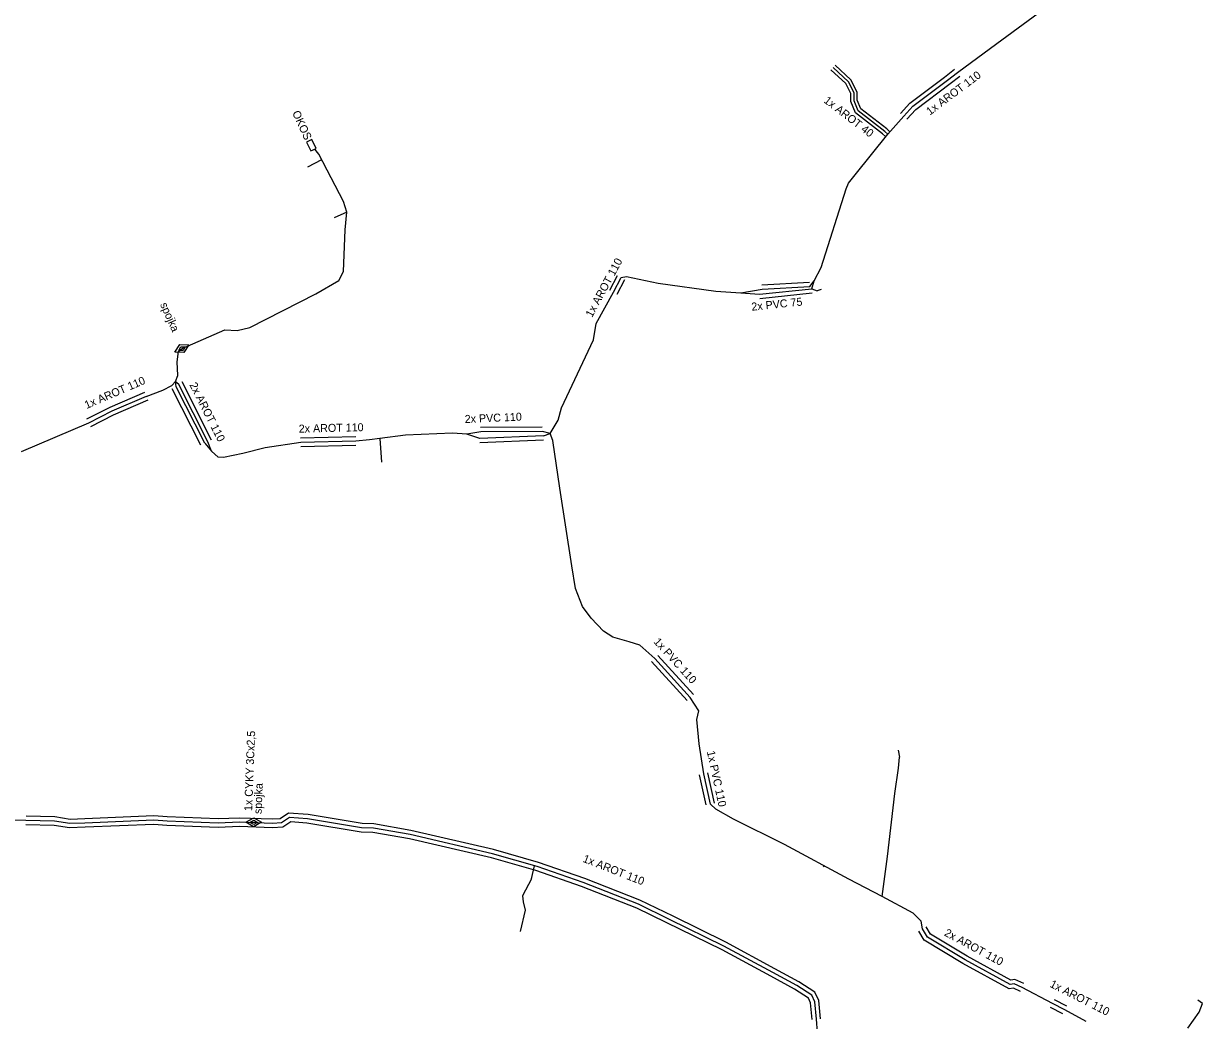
# Model space of a CAD drawing. Extents: x -651943 to -618711, y -1138561 to -1100552.
# Drawn here: x -651118.5 to -651008.1, y -1113424.7 to -1113331.3 of the extents above; entities that cross this region are included whole.
import ezdxf

# ---------------------------------------------------------------- set-up
doc = ezdxf.new("R2010")
doc.units = 0
doc.layers.add('KT trasa', color=7, linetype='Continuous')
doc.layers.add('KT zařízení', color=7, linetype='Continuous')

# ---------------------------------------------------------------- blocks, each defined once
blk = doc.blocks.new('TVSPO_1')
at = {"layer": 'KT zařízení'}
for p, q in [((-0.074, 0.002), (0, 0.044)), ((-0.001, -0.041), (-0.074, 0.002)), ((-0.035, 0), (0, 0.02)), ((0.073, 0.001), (-0.001, -0.041)), ((0, 0.044), (0.073, 0.001)), ((0, 0.02), (0.035, 0)), ((0.035, 0), (0, -0.02)), ((0, -0.02), (-0.035, 0))]:
    blk.add_line(p, q, dxfattribs=at)

msp = doc.modelspace()

# ---------------------------------------------------------------- linework, layer by layer
at = {"layer": 'KT trasa'}
for p, q in [((-651027.31, -1113333.15), (-651020.18, -1113327.9)), ((-651031.02, -1113335.89), (-651027.31, -1113333.15)), ((-651041.22, -1113336.74), (-651042.66, -1113335.41)), ((-651031.94, -1113336.61), (-651031.02, -1113335.89)), ((-651040.69, -1113337.79), (-651041.22, -1113336.74)), ((-651035.18, -1113339.04), (-651031.94, -1113336.61)), ((-651040.7, -1113338.54), (-651040.69, -1113337.79)), ((-651040.3, -1113339.48), (-651040.7, -1113338.54)), ((-651037.82, -1113341.39), (-651040.3, -1113339.48)), ((-651036.03, -1113339.98), (-651035.18, -1113339.04)), ((-651037.54, -1113341.66), (-651036.03, -1113339.98)), ((-651040.6, -1113345.48), (-651037.54, -1113341.66)), ((-651037.54, -1113341.66), (-651037.82, -1113341.39)), ((-651090.85, -1113343.52), (-651091.24, -1113343.05)), ((-651091.89, -1113344.7), (-651090.59, -1113344.03)), ((-651088.54, -1113347.97), (-651090.85, -1113343.52)), ((-651041.45, -1113346.78), (-651041.21, -1113346.25)), ((-651041.21, -1113346.25), (-651040.6, -1113345.48)), ((-651043.77, -1113354.14), (-651041.45, -1113346.78)), ((-651088.24, -1113348.95), (-651088.54, -1113347.97)), ((-651088.24, -1113348.95), (-651089.42, -1113349.48)), ((-651088.39, -1113350.61), (-651088.24, -1113348.95)), ((-651088.54, -1113354.51), (-651088.39, -1113350.61)), ((-651044.45, -1113355.41), (-651043.77, -1113354.14)), ((-651088.97, -1113355.37), (-651088.54, -1113354.51)), ((-651063.24, -1113356.45), (-651062.51, -1113355.09)), ((-651062.51, -1113355.09), (-651062.03, -1113355)), ((-651062.03, -1113355), (-651059.06, -1113355.61)), ((-651091.14, -1113356.6), (-651088.97, -1113355.37)), ((-651059.06, -1113355.61), (-651053.66, -1113356.36)), ((-651053.66, -1113356.36), (-651051.32, -1113356.51)), ((-651051.32, -1113356.51), (-651049.32, -1113356.18)), ((-651049.55, -1113356.64), (-651044.66, -1113356.13)), ((-651049.32, -1113356.18), (-651044.83, -1113355.93)), ((-651044.83, -1113355.93), (-651044.45, -1113355.41)), ((-651044.66, -1113356.13), (-651044.45, -1113355.41)), ((-651044.66, -1113356.13), (-651044.17, -1113356.34)), ((-651043.78, -1113356.22), (-651044.17, -1113356.34)), ((-651097.32, -1113359.78), (-651091.14, -1113356.6)), ((-651064.87, -1113359.39), (-651063.24, -1113356.45)), ((-651051.32, -1113356.51), (-651049.55, -1113356.64)), ((-651065.12, -1113360.91), (-651064.87, -1113359.39)), ((-651103.67, -1113361.74), (-651099.65, -1113360)), ((-651099.65, -1113360), (-651098.51, -1113360.04)), ((-651098.51, -1113360.04), (-651097.32, -1113359.78)), ((-651104.02, -1113362.03), (-651103.67, -1113361.74)), ((-651068.13, -1113367.3), (-651065.12, -1113360.91)), ((-651104.14, -1113362.99), (-651104.02, -1113362.03)), ((-651104.06, -1113364.25), (-651104.14, -1113362.99)), ((-651105.49, -1113365.64), (-651104.62, -1113365.2)), ((-651104.62, -1113365.2), (-651104.28, -1113364.84)), ((-651104.28, -1113364.84), (-651104.06, -1113364.25)), ((-651104.22, -1113365.34), (-651104.28, -1113364.84)), ((-651104.28, -1113364.84), (-651104.01, -1113365.05)), ((-651101.26, -1113370.49), (-651104.01, -1113365.05)), ((-651107.03, -1113366.22), (-651110.27, -1113367.62)), ((-651107.03, -1113366.22), (-651105.49, -1113365.64)), ((-651101.55, -1113370.61), (-651104.22, -1113365.34)), ((-651068.44, -1113368.45), (-651068.13, -1113367.3)), ((-651110.27, -1113367.62), (-651112.43, -1113368.73)), ((-651069.17, -1113369.69), (-651068.44, -1113368.45)), ((-651112.43, -1113368.73), (-651118.74, -1113371.4)), ((-651078.34, -1113369.66), (-651082.74, -1113369.85)), ((-651076.98, -1113369.75), (-651078.34, -1113369.66)), ((-651075.69, -1113369.53), (-651076.98, -1113369.75)), ((-651069.91, -1113369.52), (-651075.69, -1113369.53)), ((-651069.17, -1113369.69), (-651069.91, -1113369.52)), ((-651069.81, -1113369.91), (-651069.17, -1113369.69)), ((-651068.94, -1113370.35), (-651069.17, -1113369.69)), ((-651101.55, -1113370.61), (-651100.92, -1113371.36)), ((-651100.92, -1113371.36), (-651101.26, -1113370.49)), ((-651092.55, -1113370.54), (-651095.89, -1113371.03)), ((-651087.38, -1113370.42), (-651092.55, -1113370.54)), ((-651086.12, -1113370.29), (-651087.38, -1113370.42)), ((-651085.13, -1113370.18), (-651086.12, -1113370.29)), ((-651082.74, -1113369.85), (-651085.13, -1113370.18)), ((-651085.13, -1113370.18), (-651084.97, -1113372.38)), ((-651075.77, -1113370.17), (-651076.98, -1113369.75)), ((-651069.81, -1113369.91), (-651075.77, -1113370.17)), ((-651068.28, -1113374.83), (-651068.94, -1113370.35)), ((-651100.29, -1113371.91), (-651100.92, -1113371.36)), ((-651097.98, -1113371.56), (-651099.79, -1113371.96)), ((-651095.89, -1113371.03), (-651097.98, -1113371.56)), ((-651099.79, -1113371.96), (-651100.29, -1113371.91)), ((-651067.14, -1113382.11), (-651068.28, -1113374.83)), ((-651066.8, -1113384.23), (-651067.14, -1113382.11)), ((-651066.14, -1113385.89), (-651066.8, -1113384.23)), ((-651065.32, -1113386.99), (-651066.14, -1113385.89)), ((-651064.18, -1113388.21), (-651065.32, -1113386.99)), ((-651063.32, -1113388.78), (-651064.18, -1113388.21)), ((-651061.76, -1113389.22), (-651063.32, -1113388.78)), ((-651060.78, -1113389.54), (-651061.76, -1113389.22)), ((-651059.37, -1113390.78), (-651060.78, -1113389.54)), ((-651056.05, -1113394.43), (-651059.37, -1113390.78)), ((-651055.26, -1113395.68), (-651056.05, -1113394.43)), ((-651055.42, -1113396.49), (-651055.26, -1113395.68)), ((-651055.21, -1113398.78), (-651055.42, -1113396.49)), ((-651054.77, -1113401.58), (-651055.21, -1113398.78)), ((-651036.58, -1113399.37), (-651036.45, -1113400.01)), ((-651036.54, -1113401.06), (-651036.45, -1113400.01)), ((-651054.16, -1113404.41), (-651054.77, -1113401.58)), ((-651036.87, -1113403.41), (-651036.54, -1113401.06)), ((-651037.56, -1113409.33), (-651036.87, -1113403.41)), ((-651053.64, -1113404.9), (-651054.16, -1113404.41)), ((-651052.01, -1113405.84), (-651053.64, -1113404.9)), ((-651118.3, -1113405.95), (-651122.01, -1113405.87)), ((-651115.63, -1113406.01), (-651118.3, -1113405.95)), ((-651114.2, -1113406.25), (-651115.63, -1113406.01)), ((-651106.32, -1113405.93), (-651112.77, -1113406.19)), ((-651105.08, -1113406.02), (-651106.32, -1113405.93)), ((-651100.28, -1113406.2), (-651105.08, -1113406.02)), ((-651098.3, -1113406.12), (-651100.28, -1113406.2)), ((-651095.21, -1113406.24), (-651098.3, -1113406.12)), ((-651093.6, -1113405.67), (-651094.36, -1113406.18)), ((-651091.92, -1113405.8), (-651093.6, -1113405.67)), ((-651086.85, -1113406.64), (-651091.92, -1113405.8)), ((-651047.21, -1113408.19), (-651052.01, -1113405.84)), ((-651112.77, -1113406.19), (-651114.2, -1113406.25)), ((-651094.36, -1113406.18), (-651095.21, -1113406.24)), ((-651085.74, -1113406.68), (-651086.85, -1113406.64)), ((-651082.3, -1113407.28), (-651085.74, -1113406.68)), ((-651074.59, -1113409.07), (-651082.3, -1113407.28)), ((-651041.2, -1113411.46), (-651047.21, -1113408.19)), ((-651070.39, -1113410.26), (-651074.59, -1113409.07)), ((-651038.07, -1113413.06), (-651037.56, -1113409.33)), ((-651070.93, -1113411.43), (-651070.63, -1113410.19)), ((-651066.08, -1113411.76), (-651070.39, -1113410.26)), ((-651043.54, -1113410.19), (-651043.6, -1113410.3)), ((-651070.93, -1113411.43), (-651071.76, -1113413.01)), ((-651038.07, -1113413.06), (-651041.2, -1113411.46)), ((-651060.91, -1113413.8), (-651066.08, -1113411.76)), ((-651071.76, -1113413.01), (-651071.7, -1113413.57)), ((-651071.7, -1113413.57), (-651071.53, -1113414.34)), ((-651057.98, -1113415.22), (-651060.91, -1113413.8)), ((-651035.15, -1113414.63), (-651038.07, -1113413.06)), ((-651071.53, -1113414.34), (-651072, -1113416.36)), ((-651034.4, -1113415.37), (-651035.15, -1113414.63)), ((-651052.89, -1113417.72), (-651057.98, -1113415.22)), ((-651034.27, -1113416.11), (-651034.4, -1113415.37)), ((-651033.82, -1113416.89), (-651034.27, -1113416.11)), ((-651030.29, -1113419.02), (-651033.82, -1113416.89)), ((-651048.32, -1113420.2), (-651052.89, -1113417.72)), ((-651026.07, -1113421.31), (-651030.29, -1113419.02)), ((-651046.07, -1113421.42), (-651048.32, -1113420.2)), ((-651044.67, -1113422.32), (-651046.07, -1113421.42)), ((-651025.68, -1113421.26), (-651026.07, -1113421.31)), ((-651024.93, -1113421.59), (-651025.68, -1113421.26)), ((-651022.1, -1113423.11), (-651024.93, -1113421.59)), ((-651044.38, -1113422.94), (-651044.67, -1113422.32)), ((-651044.23, -1113424.56), (-651044.38, -1113422.94)), ((-651020.94, -1113423.7), (-651022.1, -1113423.11)), ((-651018.96, -1113424.77), (-651020.94, -1113423.7)), ((-651008.05, -1113423.09), (-651008.48, -1113422.79)), ((-651008.37, -1113423.92), (-651008.05, -1113423.09)), ((-651044.14, -1113425.8), (-651044.23, -1113424.56)), ((-651009.42, -1113425.42), (-651008.37, -1113423.92))]:
    msp.add_line(p, q, dxfattribs=at)
at = {"layer": 'KT zařízení'}
for p, q in [((-651040.99, -1113336.56), (-651042.47, -1113335.18)), ((-651041.47, -1113336.92), (-651042.86, -1113335.64)), ((-651035.46, -1113338.74), (-651032.21, -1113336.31)), ((-651032.21, -1113336.31), (-651031.28, -1113335.57)), ((-651031.7, -1113336.92), (-651030.78, -1113336.21)), ((-651041, -1113337.86), (-651041.47, -1113336.92)), ((-651040.4, -1113337.72), (-651040.99, -1113336.56)), ((-651034.92, -1113339.34), (-651031.7, -1113336.92)), ((-651041.01, -1113338.6), (-651041, -1113337.86)), ((-651040.56, -1113339.67), (-651041.01, -1113338.6)), ((-651040.41, -1113338.48), (-651040.4, -1113337.72)), ((-651040.06, -1113339.29), (-651040.41, -1113338.48)), ((-651036.34, -1113339.71), (-651035.46, -1113338.74)), ((-651038.02, -1113341.62), (-651040.56, -1113339.67)), ((-651037.64, -1113341.16), (-651040.06, -1113339.29)), ((-651035.74, -1113340.25), (-651034.92, -1113339.34)), ((-651037.76, -1113341.88), (-651038.02, -1113341.62)), ((-651037.34, -1113341.44), (-651037.64, -1113341.16)), ((-651091.51, -1113342.14), (-651092, -1113342.4)), ((-651092, -1113342.4), (-651091.62, -1113343.22)), ((-651091.62, -1113343.22), (-651091.12, -1113342.99)), ((-651091.12, -1113342.99), (-651091.51, -1113342.14)), ((-651063.6, -1113356.26), (-651062.87, -1113354.9)), ((-651062.9, -1113356.64), (-651062.17, -1113355.28)), ((-651049.35, -1113355.78), (-651044.86, -1113355.53)), ((-651049.52, -1113357.04), (-651044.63, -1113356.53)), ((-651100.91, -1113370.31), (-651103.66, -1113364.87)), ((-651107.2, -1113365.85), (-651110.44, -1113367.25)), ((-651101.92, -1113370.79), (-651104.59, -1113365.52)), ((-651110.44, -1113367.25), (-651112.62, -1113368.37)), ((-651106.88, -1113366.59), (-651110.12, -1113367.99)), ((-651110.12, -1113367.99), (-651112.26, -1113369.08)), ((-651069.92, -1113369.12), (-651075.7, -1113369.13)), ((-651087.4, -1113370.02), (-651092.57, -1113370.14)), ((-651069.8, -1113370.31), (-651075.76, -1113370.57)), ((-651087.38, -1113370.82), (-651092.55, -1113370.94)), ((-651055.76, -1113394.16), (-651059.08, -1113390.51)), ((-651056.35, -1113394.7), (-651059.68, -1113391.05)), ((-651054.56, -1113404.49), (-651055.17, -1113401.66)), ((-651053.78, -1113404.32), (-651054.39, -1113401.5)), ((-651115.59, -1113405.61), (-651118.29, -1113405.55)), ((-651114.17, -1113405.85), (-651115.59, -1113405.61)), ((-651112.79, -1113405.79), (-651114.17, -1113405.85)), ((-651106.32, -1113405.53), (-651112.79, -1113405.79)), ((-651105.06, -1113405.62), (-651106.32, -1113405.53)), ((-651100.28, -1113405.8), (-651105.06, -1113405.62)), ((-651098.3, -1113405.72), (-651100.28, -1113405.8)), ((-651095.22, -1113405.84), (-651098.3, -1113405.72)), ((-651094.49, -1113405.79), (-651095.22, -1113405.84)), ((-651093.71, -1113405.26), (-651094.49, -1113405.79)), ((-651093.49, -1113406.08), (-651094.23, -1113406.57)), ((-651091.87, -1113405.4), (-651093.71, -1113405.26)), ((-651091.97, -1113406.2), (-651093.49, -1113406.08)), ((-651086.81, -1113406.24), (-651091.87, -1113405.4)), ((-651115.67, -1113406.41), (-651118.31, -1113406.35)), ((-651114.23, -1113406.65), (-651115.67, -1113406.41)), ((-651112.75, -1113406.59), (-651114.23, -1113406.65)), ((-651106.32, -1113406.33), (-651112.75, -1113406.59)), ((-651105.09, -1113406.42), (-651106.32, -1113406.33)), ((-651100.28, -1113406.6), (-651105.09, -1113406.42)), ((-651098.3, -1113406.52), (-651100.28, -1113406.6)), ((-651095.2, -1113406.64), (-651098.3, -1113406.52)), ((-651094.23, -1113406.57), (-651095.2, -1113406.64)), ((-651086.89, -1113407.04), (-651091.97, -1113406.2)), ((-651085.79, -1113407.08), (-651086.89, -1113407.04)), ((-651085.69, -1113406.28), (-651086.81, -1113406.24)), ((-651082.37, -1113407.67), (-651085.79, -1113407.08)), ((-651082.23, -1113406.89), (-651085.69, -1113406.28)), ((-651074.49, -1113408.68), (-651082.23, -1113406.89)), ((-651074.69, -1113409.46), (-651082.37, -1113407.67)), ((-651070.51, -1113410.64), (-651074.69, -1113409.46)), ((-651070.27, -1113409.88), (-651074.49, -1113408.68)), ((-651065.93, -1113411.39), (-651070.27, -1113409.88)), ((-651066.23, -1113412.13), (-651070.51, -1113410.64)), ((-651060.76, -1113413.43), (-651065.93, -1113411.39)), ((-651061.06, -1113414.17), (-651066.23, -1113412.13)), ((-651057.65, -1113414.93), (-651060.76, -1113413.43)), ((-651058.3, -1113415.51), (-651061.06, -1113414.17)), ((-651052.72, -1113417.36), (-651057.65, -1113414.93)), ((-651053.06, -1113418.08), (-651058.3, -1113415.51)), ((-651033.54, -1113416.6), (-651033.93, -1113415.91)), ((-651034.12, -1113417.18), (-651034.63, -1113416.31)), ((-651030.5, -1113419.36), (-651034.12, -1113417.18)), ((-651030.1, -1113418.67), (-651033.54, -1113416.6)), ((-651048.51, -1113420.55), (-651053.06, -1113418.08)), ((-651048.13, -1113419.85), (-651052.72, -1113417.36)), ((-651026.16, -1113421.72), (-651030.5, -1113419.36)), ((-651026, -1113420.9), (-651030.1, -1113418.67)), ((-651045.86, -1113421.08), (-651048.13, -1113419.85)), ((-651046.28, -1113421.76), (-651048.51, -1113420.55)), ((-651044.36, -1113422.05), (-651045.86, -1113421.08)), ((-651025.63, -1113420.85), (-651026, -1113420.9)), ((-651024.78, -1113421.22), (-651025.63, -1113420.85)), ((-651044.98, -1113422.59), (-651046.28, -1113421.76)), ((-651044.77, -1113423.05), (-651044.98, -1113422.59)), ((-651043.99, -1113422.83), (-651044.36, -1113422.05)), ((-651025.75, -1113421.67), (-651026.16, -1113421.72)), ((-651025.1, -1113421.96), (-651025.75, -1113421.67)), ((-651044.63, -1113424.6), (-651044.77, -1113423.05)), ((-651043.83, -1113424.52), (-651043.99, -1113422.83)), ((-651021.13, -1113424.06), (-651022.29, -1113423.47)), ((-651020.77, -1113423.34), (-651021.93, -1113422.75))]:
    msp.add_line(p, q, dxfattribs=at)

# ---------------------------------------------------------------- block references
at = {"layer": 'KT zařízení', "xscale": 9.99998044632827, "yscale": 9.999980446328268, "rotation": 28.532887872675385}
msp.add_blockref('TVSPO_1', (-651103.68, -1113361.74), dxfattribs=at)
at = {"layer": 'KT zařízení', "xscale": 10, "yscale": 10}
msp.add_blockref('TVSPO_1', (-651096.96, -1113406.13), dxfattribs=at)

# ---------------------------------------------------------------- texts
at = {"layer": 'KT zařízení'}
for s, rotation, p in [('1x AROT 110', 36.8643, (-651033.59, -1113339.92)), ('1x AROT 40', 322.3979, (-651043.6, -1113338.63)), ('OKOS', 294.6468, (-651093.37, -1113339.65)), ('1x AROT 110', 61.7747, (-651065.25, -1113358.88)), ('spojka', 293.801, (-651105.75, -1113357.6)), ('2x PVC 75', 5.9541, (-651050.28, -1113358.2)), ('1x AROT 110', 23.3732, (-651112.62, -1113367.41)), ('2x AROT 110', 296.8173, (-651103.01, -1113365.13)), ('2x PVC 110', 2.4979, (-651077.17, -1113368.72)), ('2x AROT 110', 1.3296, (-651092.73, -1113369.62)), ('1x PVC 110', 312.2893, (-651059.53, -1113389.25)), ('1x CYKY 3Cx2,5', 87.7744, (-651097.11, -1113405.08)), ('1x PVC 110', 282.1639, (-651054.5, -1113399.5)), ('spojka', 87.7744, (-651096.22, -1113405.36)), ('1x AROT 110', 338.4704, (-651066.18, -1113409.81)), ('2x AROT 110', 331.6111, (-651032.31, -1113416.7)), ('1x AROT 110', 333.0412, (-651022.42, -1113421.51))]:
    msp.add_text(s, height=0.75, rotation=rotation, dxfattribs=at).set_placement(p)

doc.saveas('drawing.dxf')
